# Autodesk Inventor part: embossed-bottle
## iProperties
Shininess: 64.0
Length Units: 11269
Angle Units: 11279
Time Units: 11290
Mass Units: 11283
Length Display Precision: 3
Angle Display Precision: 2
Compacted: True
Part Number: embossed-bottle
Document SubType Name: Modeling
Created: 2002-12
Designer: deepak
Density: 1 g/cm^3
Density: 0.0
Volumn: 0.0
Area: 0.0
PropertySet Name: Model Information
Control State: 0
Master: False
Checked Out: False
Author: deepak
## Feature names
1. Revolution1
2. Fillet1
